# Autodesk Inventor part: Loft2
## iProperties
Shininess: 64.0
Length Units: 11269
Angle Units: 11279
Time Units: 11290
Mass Units: 11283
Length Display Precision: 3
Angle Display Precision: 2
Compacted: True
Created: 2002-08
Part Number: Loft2
Document SubType Name: Modeling
Designer: Franz Kaltseis
Density: 1 g/cm^3
Density: 0.0
Volumn: 0.0
Area: 0.0
PropertySet Name: Model Information
Control State: 0
Master: False
Checked Out: False
Author: Franz Kaltseis
